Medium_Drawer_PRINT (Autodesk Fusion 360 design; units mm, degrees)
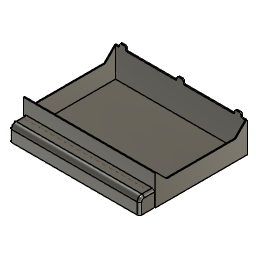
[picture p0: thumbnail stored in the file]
sketch "Sketch1" plane through (0, 0, 0) normal (0, 0, 1) x axis (1, 0, 0)
  line L1 (113.9, 0) -> (0, 0)
  line L2 (113.9, 80) -> (113.9, 0)
  line L3 (0, 80) -> (113.9, 80)
  line L4 (0, 0) -> (0, 80)
  point P1 (0, 0)
  point P2 (0, 0)
  point P3 (113.9, 0)
  point P4 (113.9, 80)
  horizontal L1
  vertical L2
  horizontal L3
  vertical L4
  coincident P1 P2
  dimension "d1" distance P2 P3 = 113.9 (= "114.7 mm - 0.8 mm")
  dimension "d2" distance P3 P4 = 80
extrude "Extrude1" new body sketch "Sketch1" along normal blind 26.2
shell "Shell1" innerThickness 0.8
work_plane "WorkPlane1" AlongDistance -18.4
sketch "Sketch3" plane through (0, 80, 0) normal (0, 1, 0) x axis (-1, 0, 0)
  line L1 (0, 0) -> (-113.9, 0)
  line L2 (0, 26.2) -> (0, 0)
  line L3 (-113.9, 26.2) -> (0, 26.2)
  line L4 (-113.9, 0) -> (-113.9, 26.2)
  line L5 (-56.95, 0) -> (-56.95, 26.2)
  line L6 (-109.65, 28.45) -> (-109.65, 27.45)
  line L7 (-105.4, 29.7) -> (-108.4, 29.7)
  line L8 (-104.15, 27.45) -> (-104.15, 28.45)
  line L9 (-102.9, 26.2) -> (-110.9, 26.2)
  line L10 (-8.5, 29.7) -> (-5.5, 29.7)
  line L11 (-4.25, 28.45) -> (-4.25, 27.45)
  line L12 (-11, 26.2) -> (-3, 26.2)
  line L13 (-9.75, 27.45) -> (-9.75, 28.45)
  line L14 (-55.25, 29.7) -> (-58.25, 29.7)
  line L15 (-59.5, 28.45) -> (-59.5, 27.45)
  line L16 (-52.75, 26.2) -> (-60.75, 26.2)
  line L17 (-54, 27.45) -> (-54, 28.45)
  arc A1 centre (-110.9, 27.45) radius 1.25 clockwise from (-109.65, 27.45) to (-110.9, 26.2)
  arc A2 centre (-108.4, 28.45) radius 1.25 clockwise from (-109.65, 28.45) to (-108.4, 29.7)
  arc A3 centre (-105.4, 28.45) radius 1.25 clockwise from (-105.4, 29.7) to (-104.15, 28.45)
  arc A4 centre (-102.9, 27.45) radius 1.25 clockwise from (-102.9, 26.2) to (-104.15, 27.45)
  arc A5 centre (-5.5, 28.45) radius 1.25 clockwise from (-5.5, 29.7) to (-4.25, 28.45)
  arc A6 centre (-11, 27.45) radius 1.25 clockwise from (-9.75, 27.45) to (-11, 26.2)
  arc A7 centre (-3, 27.45) radius 1.25 clockwise from (-3, 26.2) to (-4.25, 27.45)
  arc A8 centre (-8.5, 28.45) radius 1.25 clockwise from (-9.75, 28.45) to (-8.5, 29.7)
  arc A9 centre (-58.25, 28.45) radius 1.25 clockwise from (-59.5, 28.45) to (-58.25, 29.7)
  arc A10 centre (-60.75, 27.45) radius 1.25 clockwise from (-59.5, 27.45) to (-60.75, 26.2)
  arc A11 centre (-52.75, 27.45) radius 1.25 clockwise from (-52.75, 26.2) to (-54, 27.45)
  arc A12 centre (-55.25, 28.45) radius 1.25 clockwise from (-55.25, 29.7) to (-54, 28.45)
  point P10 (-56.95, 26.2)
  point P11 (-56.95, 0)
  point P20 (-106.9, 29.7)
  point P12 (-109.65, 27.45)
  point P27 (-4.25, 27.45)
  point P13 (-109.65, 28.45)
  point P21 (-4.25, 28.45)
  point P14 (-108.4, 29.7)
  point P28 (-5.5, 29.7)
  point P15 (-105.4, 29.7)
  point P26 (-8.5, 29.7)
  point P16 (-104.15, 28.45)
  point P23 (-9.75, 28.45)
  point P17 (-104.15, 27.45)
  point P22 (-9.75, 27.45)
  point P18 (-110.9, 26.2)
  point P30 (-3, 26.2)
  point P19 (-102.9, 26.2)
  point P29 (-11, 26.2)
  point P31 (-7, 29.7)
  point P44 (-60.75, 26.2)
  point P45 (-52.75, 26.2)
  point P36 (-58.25, 29.7)
  point P40 (-55.25, 29.7)
  midpoint L3 P10
  perpendicular L3 L5
  coincident L1 P11
  horizontal L7
  tangent L7 A2
  tangent L6 A2
  tangent L6 A1
  tangent L7 A3
  tangent L8 A3
  tangent L8 A4
  tangent L9 A4
  tangent L9 A1
  equal A1 A2
  equal A2 A3
  equal A3 A4
  collinear L3 L9
  vertical L8
  vertical L6
  midpoint L7 P20
  symmetric L5 P12 P27
  symmetric L5 P13 P21
  symmetric L5 P14 P28
  symmetric L5 P15 P26
  symmetric L5 P16 P23
  symmetric L5 P17 P22
  symmetric L5 P18 P30
  symmetric L5 P19 P29
  symmetric L5 P20 P31
  symmetric L5 A1 A7
  symmetric L5 A2 A5
  symmetric L5 A3 A8
  symmetric L5 A4 A6
  horizontal L14
  tangent L14 A9
  tangent A9 L15
  tangent L15 A10
  tangent L14 A12
  tangent L17 A12
  tangent A11 L17
  tangent A11 L16
  tangent A10 L16
  equal A9 A10
  equal A9 A12
  equal A11 A12
  vertical L17
  vertical L15
  dimension "d18" distance L4 P20 = 7
  dimension "d19" distance L7 L9 = 3.5
  dimension "d20" distance L6 L8 = 5.5
  dimension "d21" radius A1 = 1.25
  dimension "d62" distance L14 L16 = 3.5
  dimension "d63" distance L15 L17 = 5.5
  dimension "d64" radius A10 = 1.25
  dimension "d65" = 114.3
  dimension "d66" distance L8 L15 = 44.65
  dimension "d67" = 44.8
  dimension "d68" distance P44 P45 = 8
  dimension "d69" radius A11 = 1.25
  dimension "d70" distance P36 P40 = 3
  dimension "d71" radius A12 = 1.25
  dimension "d72" radius A10 = 1.25
  dimension "d73" radius A9 = 1.25
  dimension "d74" distance P10 L14 = 3.5
extrude "Extrude3" add sketch "Sketch3" profile of L3 A1 A2 A3 A4 L6 L7 L8 L9 A5 L10 A6 A7 L11 L12 A8 L13 L14 A9 L15 A10 A11 L16 L17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 against normal blind 0.8
sketch "Sketch4" plane through (113.9, 0, 0) normal (1, 0, 0) x axis (0, 1, 0)
  line L1 (80, 0) -> (0, 0)
  line L2 (80, 26.2) -> (80, 0)
  line L3 (0, 26.2) -> (80, 26.2)
  line L4 (0, 0) -> (0, 26.2)
  line L5 (10.1071, 17) -> (0.9071, 26.2)
  line L6 (7.8528, 26.2) -> (0.9071, 26.2)
  line L7 (69.7311, 17) -> (10.1071, 17)
  line L8 (78.9311, 26.2) -> (69.7311, 17)
  line L9 (0.9071, 26.2) -> (78.9311, 26.2)
  point P6 (0.9071, 26.2)
  point P10 (78.9311, 26.2)
  horizontal L6
  coincident L3 P6
  horizontal L7
  coincident L3 P10
  dimension "d24" angle L5 L6 = 45
  dimension "d25" angle L7 L8 = 135
  dimension "d26" distance L1 L7 = 17
extrude "Extrude4" cut sketch "Sketch4" profile of L3 L5 L7 L8 L9 to an object
extrude "Extrude5" add of existing geometry blind 0.4
sketch "Sketch5" plane through (0, 0, 0) normal (0, -1, 0) x axis (1, 0, 0)
  line L1 (113.9, 0) -> (0, 0)
  line L2 (113.9, 26.2) -> (113.9, 0)
  line L3 (0, 26.2) -> (113.9, 26.2)
  line L4 (0, 0) -> (0, 26.2)
  line L5 (113.4, 13.8) -> (0.5, 13.8)
  line L6 (113.4, 13) -> (113.4, 13.8)
  line L7 (0.5, 13) -> (113.4, 13)
  line L8 (0.5, 13.8) -> (0.5, 13)
  horizontal L5
  vertical L6
  horizontal L7
  vertical L8
  dimension "d31" distance L4 L8 = 0.5
  dimension "d32" distance L2 L6 = 0.5
  dimension "d33" distance L5 L7 = 0.8
  dimension "d34" distance L1 L7 = 13
extrude "Extrude6" add sketch "Sketch5" profile of L5 L6 L7 L8 along normal blind 13
sketch "Sketch6" plane through (0, 0, 13) normal (0, 0, -1) x axis (1, 0, 0)
  line L1 (113.4, 0) -> (0.5, 0)
  line L2 (113.4, 13) -> (113.4, 0)
  line L3 (0.5, 13) -> (113.4, 13)
  line L4 (0.5, 0) -> (0.5, 13)
  line L5 (31.3, 13) -> (0.5, 13)
  line L6 (0.5, 12.2) -> (31.3, 12.2)
  line L7 (0.5, 13) -> (0.5, 12.2)
  line L8 (113.4, 13) -> (31.3, 13)
  line L9 (113.4, 12.2) -> (31.3, 12.2)
  line L10 (113.4, 13) -> (113.4, 12.2)
  point P5 (0.5, 13)
  point P6 (0.5, 13)
  point P4 (113.4, 13)
  point P10 (113.4, 13)
  point P11 (113.4, 12.2)
  point P9 (0.5, 12.2)
  horizontal L5
  horizontal L6
  vertical L7
  coincident P5 P6
  coincident P4 P10
  coincident L2 P11
  perpendicular L2 L9
  dimension "d37" distance P6 P9 = 0.8
extrude "Extrude7" add sketch "Sketch6" profile of L2 L3 L4 L5 L6 L7 L8 L9 L10 along normal blind 13
sketch "Sketch8" plane through (0, 0, 13) normal (0, 0, -1) x axis (1, 0, 0)
  line L1 (0.5, 12.2) -> (113.4, 12.2)
  line L2 (0.5, 0) -> (0.5, 12.2)
  line L3 (113.4, 0) -> (0.5, 0)
  line L4 (113.4, 12.2) -> (113.4, 0)
  line L5 (0.5, 0) -> (1.3, 0)
  line L6 (0.5, 12.2) -> (0.5, 0)
  line L7 (1.3, 12.2) -> (0.5, 12.2)
  line L8 (1.3, 0) -> (1.3, 12.2)
  line L9 (112.6, 0) -> (113.4, 0)
  line L10 (112.6, 12.2) -> (112.6, 0)
  line L11 (113.4, 12.2) -> (112.6, 12.2)
  line L12 (113.4, 0) -> (113.4, 12.2)
  point P3 (0.5, 12.2)
  point P8 (0.5, 12.2)
  point P6 (1.3, 0)
  point P12 (112.6, 12.2)
  point P5 (113.4, 0)
  point P10 (113.4, 0)
  point P13 (113.4, 12.2)
  point P9 (1.3, 12.2)
  horizontal L5
  vertical L6
  horizontal L7
  vertical L8
  coincident P3 P8
  coincident L3 P6
  horizontal L9
  vertical L10
  horizontal L11
  vertical L12
  coincident L1 P12
  coincident P5 P10
  dimension "d45" distance P12 P13 = 0.8
  dimension "d46" distance P8 P9 = 0.8
extrude "Extrude9" add sketch "Sketch8" along normal blind 13
fillet "Fillet2" radius 4
chamfer "Chamfer1" distance 3
fillet "Fillet4" radius 2
fillet "Fillet5" radius 2
fillet "Fillet6" radius 2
